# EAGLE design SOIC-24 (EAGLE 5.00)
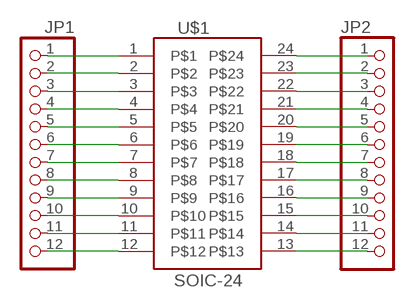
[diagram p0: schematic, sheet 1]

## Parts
JP1  PINHD-1X12  [1X12]
JP2  PINHD-1X12  [1X12]
U$1  SOIC-24  [SOIC-24]

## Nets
N$1: JP1.1 U$1.1
N$2: JP1.2 U$1.2
N$3: JP1.3 U$1.3
N$4: JP1.4 U$1.4
N$5: JP1.5 U$1.5
N$6: JP1.6 U$1.6
N$7: JP1.7 U$1.7
N$8: JP1.8 U$1.8
N$9: JP1.9 U$1.9
N$10: JP1.10 U$1.10
N$11: JP1.11 U$1.11
N$12: JP1.12 U$1.12
N$13: JP2.1 U$1.24
N$14: JP2.2 U$1.23
N$15: JP2.3 U$1.22
N$16: JP2.4 U$1.21
N$17: JP2.5 U$1.20
N$18: JP2.6 U$1.19
N$19: JP2.7 U$1.18
N$20: JP2.8 U$1.17
N$21: JP2.9 U$1.16
N$22: JP2.10 U$1.15
N$23: JP2.11 U$1.14
N$24: JP2.12 U$1.13

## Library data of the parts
JP1 JP2 = pinhead:PINHD-1X12: PIN HEADER
U$1 = smd:SOIC-24

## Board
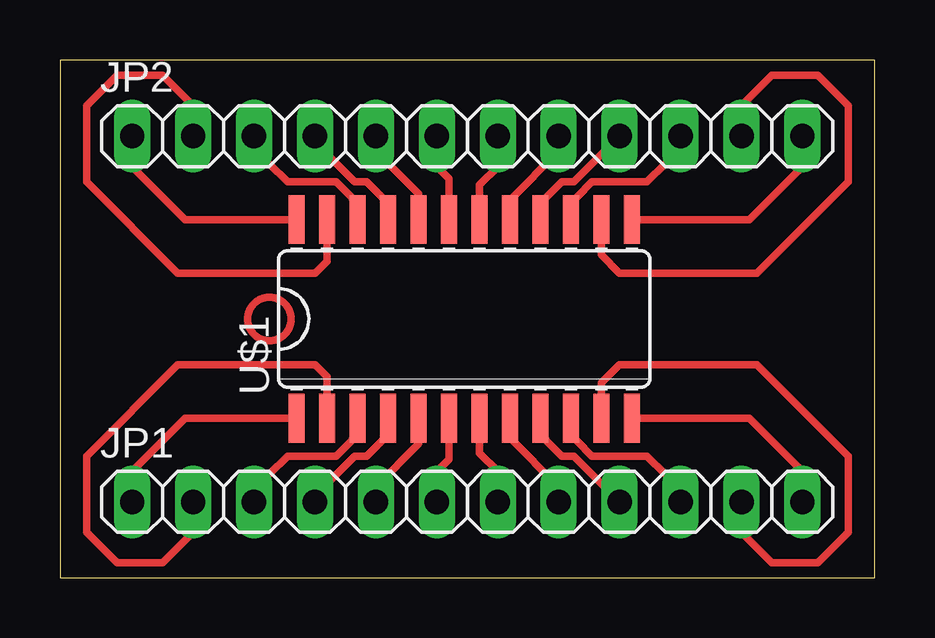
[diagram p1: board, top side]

Size 33.96 x 21.58 mm. Coordinates in mm from the lower left corner, seen from the top.
Outline: 0,0 33.96,0 33.96,21.58 0,21.58 0,0
Copper layers (1*16): Top 0.035mm / dielectric 1.5mm / Bottom 0.035mm
Design rules "default": minimum track width 10mil, minimum drill 24mil, track to track 8mil, track to pad 8mil, pad to pad 8mil, via to via 8mil, smd to smd 8mil, copper to edge 40mil, drill to drill 8mil, minimum pad ring 10mil, minimum via ring 8mil, stop-mask expansion 4mil, vias tented up to drill 0mil, thermal gap 10mil

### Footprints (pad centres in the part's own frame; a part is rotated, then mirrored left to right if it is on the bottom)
1X12 = drill 1.016 long: 1 -13.97,0; 2 -11.43,0; 3 -8.89,0; 4 -6.35,0; 5 -3.81,0; 6 -1.27,0; 7 1.27,0; 8 3.81,0; 9 6.35,0; 10 8.89,0; 11 11.43,0; 12 13.97,0
SOIC-24 = smd 0.66 x 2.032: 1 -6.985,-4.14; 2 -5.715,-4.14; 3 -4.445,-4.14; 4 -3.175,-4.14; 5 -1.905,-4.14; 6 -0.635,-4.14; 7 0.635,-4.14; 8 1.905,-4.14; 9 3.175,-4.14; 10 4.445,-4.14; 11 5.715,-4.14; 12 6.985,-4.14; 13 6.985,4.14; 14 5.715,4.14; 15 4.445,4.14; 16 3.175,4.14; 17 1.905,4.14; 18 0.635,4.14; 19 -0.635,4.14; 20 -1.905,4.14; 21 -3.175,4.14; 22 -4.445,4.14; 23 -5.715,4.14; 24 -6.985,4.14

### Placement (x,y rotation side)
JP1  16.98,3.17 0 top
JP2  16.98,18.41 0 top
U$1  16.85,10.79 0 top

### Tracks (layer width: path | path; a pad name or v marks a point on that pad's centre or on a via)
N$1
  Top 0.305: U$1.1 5.22,6.65 3.01,4.44 JP1.1
N$2
  Top 0.305: U$1.2 11.14,8.38 10.63,8.89 4.92,8.89 1.1,5.08 1.1,1.9 2.38,0.63 4.28,0.63 5.55,1.9 JP1.2
N$3
  Top 0.254: 12.15,5.71 U$1.3
  Top 0.305: 12.15,5.71 11.52,5.08 9.49,5.08 8.73,4.31 JP1.3
N$4
  Top 0.254: 13.42,5.71 U$1.4
  Top 0.305: 13.42,5.71 12.79,5.08 12.28,5.08 11.27,4.06 JP1.4
N$5
  Top 0.305: U$1.5 14.95,5.58 13.17,3.8 JP1.5
N$6
  Top 0.305: U$1.6 16.22,4.95 15.71,4.44 JP1.6
N$7
  Top 0.305: U$1.7 17.49,5.2 18.25,4.44 JP1.7
N$8
  Top 0.305: 18.76,5.84 20.79,3.8 JP1.8
  Top 0.406: U$1.8 18.76,5.84
N$9
  Top 0.254: U$1.9 20.28,5.71
  Top 0.305: 20.28,5.71 20.92,5.08 21.42,5.08 JP1.9
N$10
  Top 0.254: 21.55,5.71 U$1.10
  Top 0.305: 21.55,5.71 22.19,5.08 24.47,5.08 25.23,4.31 JP1.10
N$11
  Top 0.305: U$1.11 22.57,8.12 23.33,8.89 29.04,8.89 32.85,5.08 32.85,1.9 31.58,0.63 29.68,0.63 28.41,1.9 JP1.11
N$12
  Top 0.305: U$1.12 28.74,6.65 30.95,4.44 JP1.12
N$13
  Top 0.305: U$1.24 5.22,14.93 3.01,17.14 JP2.1
N$14
  Top 0.305: U$1.23 11.14,13.2 10.63,12.7 4.92,12.7 1.1,16.5 1.1,19.68 2.38,20.95 4.28,20.95 5.55,19.68 JP2.2
N$15
  Top 0.254: U$1.22 12.15,15.87
  Top 0.305: 12.15,15.87 11.52,16.5 9.49,16.5 8.73,17.27 JP2.3
N$16
  Top 0.254: U$1.21 13.42,15.87
  Top 0.305: 13.42,15.87 12.79,16.5 12.28,16.5 11.27,17.52 JP2.4
N$17
  Top 0.305: U$1.20 14.95,16 13.17,17.77 JP2.5
N$18
  Top 0.305: U$1.19 16.22,16.63 15.71,17.14 JP2.6
N$19
  Top 0.305: U$1.18 17.49,16.38 18.25,17.14 JP2.7
N$20
  Top 0.305: U$1.17 18.76,15.74 20.79,17.77 JP2.8
N$21
  Top 0.254: U$1.16 20.28,15.87
  Top 0.305: 20.28,15.87 20.92,16.5 21.42,16.5 JP2.9
N$22
  Top 0.254: U$1.15 21.55,15.87
  Top 0.305: 21.55,15.87 22.19,16.5 24.47,16.5 25.23,17.27 JP2.10
N$23
  Top 0.305: U$1.14 22.57,13.46 23.33,12.7 29.04,12.7 32.85,16.5 32.85,19.68 31.58,20.95 29.68,20.95 28.41,19.68
  Top 0.406: 28.41,19.68 JP2.11
N$24
  Top 0.305: U$1.13 28.74,14.93 30.95,17.14 JP2.12
(copper drawn outside any net)
  shapes: Top circle x1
